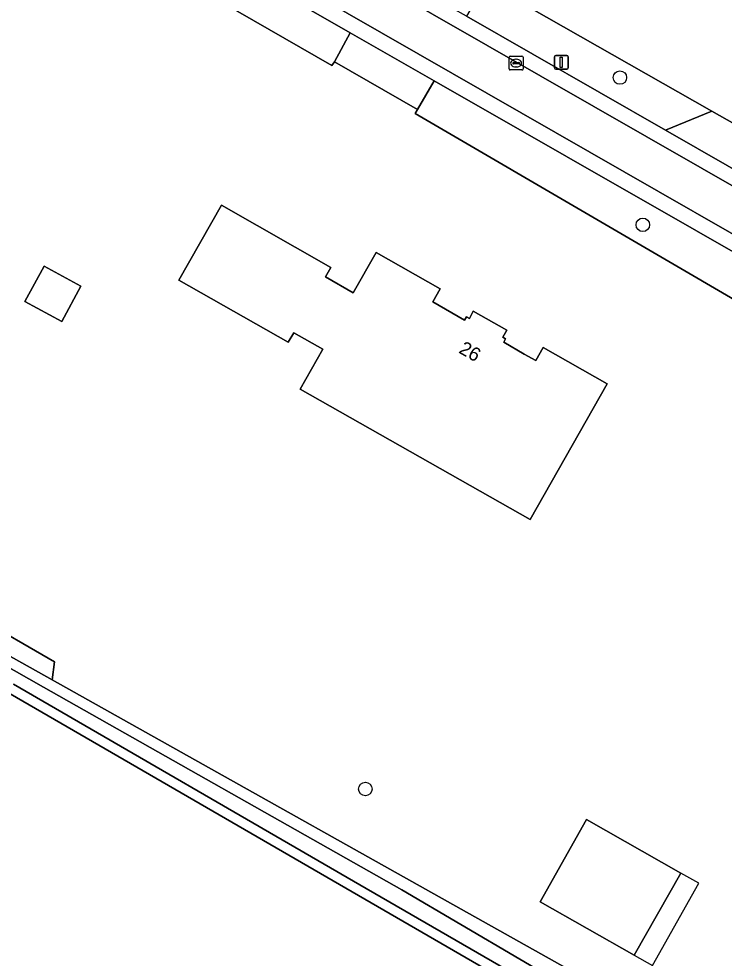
# Model space of a CAD drawing. Extents: x 156502 to 159075, y 384229 to 386100.
# Drawn here: x 157051.2 to 157102.6, y 385696.6 to 385765 of the extents above; entities that cross this region are included whole.
import ezdxf

# ---------------------------------------------------------------- set-up
doc = ezdxf.new("R2010")
doc.units = 0
for name, color, linetype in [('IMGEO_Berm_groen', 7, 'Continuous'), ('IMGEO_Boom', 7, 'Continuous'), ('IMGEO_Erf', 7, 'Continuous'), ('IMGEO_Grasland_agrarisch', 7, 'Continuous'), ('IMGEO_Groenvoorziening', 7, 'Continuous'), ('IMGEO_Hek', 7, 'Continuous'), ('IMGEO_Lichtmast', 7, 'Continuous'), ('IMGEO_Oever', 7, 'Continuous'), ('IMGEO_Pand', 7, 'Continuous'), ('IMGEO_Pand_nummerreeks', 7, 'Continuous'), ('IMGEO_Pand_overbouw', 7, 'Continuous'), ('IMGEO_Rijbaan_lokaal_gesloten', 7, 'Continuous'), ('IMGEO_Rijbaan_lokaal_halfverhard', 7, 'Continuous'), ('IMGEO_Rijbaan_lokaal_open', 7, 'Continuous'), ('IMGEO_Rioolput', 7, 'Continuous'), ('IMGEO_Waterloop', 7, 'Continuous')]:
    doc.layers.add(name, color=color, linetype=linetype)

msp = doc.modelspace()

# ---------------------------------------------------------------- linework, layer by layer
at = {"layer": 'IMGEO_Berm_groen'}
msp.add_lwpolyline([(157086.152, 385767.162), (157085.817, 385766.586), (157084.961, 385767.091), (157083.861, 385765.187), (157098.368, 385756.889), (157101.744, 385758.276)], close=True, dxfattribs=at)
at = {"layer": 'IMGEO_Boom'}
for centre in [(157095.045, 385760.722), (157096.713, 385749.995), (157076.496, 385708.898)]:
    msp.add_circle(centre, 0.489, dxfattribs=at)
at = {"layer": 'IMGEO_Erf'}
for points in [[(157048.701, 385788.533), (157057.714, 385783.415), (157062.278, 385780.824), (157070.393, 385776.216), (157073.942, 385774.201), (157084.266, 385768.252), (157086.152, 385767.162), (157101.744, 385758.276), (157104.7, 385756.591), (157109.515, 385753.847), (157111.678, 385752.607), (157114.022, 385751.264), (157119.086, 385748.362), (157121.522, 385746.887), (157123.015, 385746.039), (157125.376, 385744.699), (157127.595, 385743.439), (157130.921, 385741.579), (157131.197, 385741.421), (157144.11, 385733.995)], [(157147.432, 385715.812), (157133.773, 385723.654), (157134.821, 385725.475), (157132.597, 385726.756), (157131.792, 385725.315), (157113.077, 385736.144), (157108.687, 385738.705), (157108.063, 385741.81), (157080.131, 385758.103), (157080.304, 385758.402), (157074.239, 385761.861), (157074.046, 385761.597), (157054.491, 385772.88), (157047.62, 385771.736)], [(157042.415, 385724.776), (157053.851, 385718.152), (157053.67, 385716.85), (157130.083, 385674.016), (157162.143, 385703.286)]]:
    msp.add_lwpolyline(points, dxfattribs=at)
for points in [[(157088.51, 385728.529), (157071.737, 385738.033), (157073.388, 385740.939), (157071.275, 385742.139), (157070.88, 385741.444), (157062.916, 385745.969), (157066.013, 385751.42), (157073.979, 385746.895), (157073.583, 385746.199), (157075.603, 385745.041), (157077.286, 385747.99), (157081.958, 385745.337), (157081.417, 385744.384), (157083.732, 385743.053), (157083.873, 385743.292), (157084.077, 385743.175), (157084.364, 385743.707), (157086.808, 385742.331), (157086.514, 385741.808), (157086.713, 385741.694), (157086.579, 385741.46), (157088.072, 385740.585), (157088.91, 385740.111), (157089.452, 385741.064), (157094.116, 385738.421)], [(157054.382, 385742.96), (157051.695, 385744.412), (157053.089, 385746.991), (157055.776, 385745.538)], [(157099.476, 385702.779), (157096.086, 385696.794), (157089.222, 385700.682), (157092.613, 385706.667)]]:
    msp.add_lwpolyline(points, close=True, dxfattribs=at)
at = {"layer": 'IMGEO_Grasland_agrarisch'}
msp.add_lwpolyline([(157128.6, 385670.699), (157041.361, 385721.169), (157027.049, 385630.912), (157026.047, 385625.421)], dxfattribs=at)
at = {"layer": 'IMGEO_Groenvoorziening'}
for points in [[(157048.686, 385779.263), (157047.987, 385776.991), (157054.491, 385772.88), (157074.046, 385761.597), (157074.239, 385761.861), (157075.399, 385763.984), (157061.322, 385772.036)], [(157047.987, 385776.991), (157047.892, 385775.032), (157046.412, 385772.497), (157046.044, 385771.329), (157045.742, 385769.133), (157042.959, 385732.042), (157041.74, 385723.537), (157053.67, 385716.85), (157053.851, 385718.152), (157042.415, 385724.776), (157044.054, 385732.143), (157045.294, 385741.29), (157045.604, 385750.127), (157045.953, 385758.926), (157047.62, 385771.736), (157054.491, 385772.88)], [(157081.499, 385760.496), (157080.304, 385758.402), (157080.131, 385758.103), (157108.063, 385741.81), (157108.687, 385738.705), (157110.125, 385741.217), (157110.277, 385744.036)]]:
    msp.add_lwpolyline(points, close=True, dxfattribs=at)
at = {"layer": 'IMGEO_Hek'}
for points in [[(157074.046, 385761.597), (157054.491, 385772.88)], [(157086.152, 385767.162), (157101.744, 385758.276)], [(157108.687, 385738.705), (157108.063, 385741.81), (157080.131, 385758.103)], [(157101.744, 385758.276), (157104.7, 385756.591)]]:
    msp.add_lwpolyline(points, dxfattribs=at)
at = {"layer": 'IMGEO_Lichtmast'}
for p, q in [((157090.277, 385761.431), (157090.277, 385762.231)), ((157090.277, 385762.231), (157090.277, 385761.431)), ((157090.377, 385762.331), (157091.167, 385762.331)), ((157091.167, 385762.331), (157090.377, 385762.331)), ((157091.267, 385762.231), (157091.267, 385761.431)), ((157091.267, 385761.431), (157091.267, 385762.231)), ((157091.167, 385761.331), (157090.377, 385761.331)), ((157090.377, 385761.331), (157091.167, 385761.331))]:
    msp.add_line(p, q, dxfattribs=at)
msp.add_lwpolyline([(157090.697, 385762.206), (157090.847, 385762.206), (157090.847, 385761.456), (157090.697, 385761.456), (157090.697, 385762.206)], dxfattribs=at)
for centre, start, end in [((157090.377, 385762.231), 90, 180), ((157090.377, 385762.231), 90, 180), ((157091.167, 385762.231), 0, 90), ((157091.167, 385762.231), 360, 90), ((157090.377, 385761.431), 180, 270), ((157090.377, 385761.431), 180, 270), ((157091.167, 385761.431), 270, 0), ((157091.167, 385761.431), 270, 0)]:
    msp.add_arc(centre, 0.1, start, end, dxfattribs=at)
at = {"layer": 'IMGEO_Oever'}
for points in [[(157053.67, 385716.85), (157041.74, 385723.537)], [(157041.602, 385722.806), (157053.036, 385716.305), (157079.167, 385701.542), (157100.636, 385688.921), (157128.657, 385673.175), (157129.567, 385672.843), (157130.183, 385672.807), (157130.592, 385673.019), (157131.132, 385673.437), (157133.442, 385675.627), (157161.344, 385701.206)], [(157041.361, 385721.169), (157128.6, 385670.699)], [(157145.132, 385684.678), (157131.268, 385672.592), (157130.641, 385672.071), (157130.089, 385671.912), (157129.557, 385671.959), (157128.852, 385672.102), (157128.318, 385672.451), (157100.715, 385687.7), (157076.092, 385701.913), (157050.852, 385716.529)], [(157132.606, 385671.378), (157162.655, 385699.661), (157164.374, 385701.279), (157164.798, 385702.861), (157164.518, 385703.205), (157165.011, 385703.658), (157165.17, 385704.25), (157162.143, 385703.286), (157130.083, 385674.016), (157053.67, 385716.85)]]:
    msp.add_lwpolyline(points, dxfattribs=at)
at = {"layer": 'IMGEO_Pand'}
for points in [[(157066.013, 385751.42), (157062.916, 385745.969), (157070.88, 385741.444), (157071.275, 385742.139), (157073.388, 385740.939), (157071.737, 385738.033), (157088.51, 385728.529), (157094.116, 385738.421), (157089.452, 385741.064), (157088.91, 385740.111), (157088.072, 385740.585), (157086.579, 385741.46), (157086.713, 385741.694), (157086.514, 385741.808), (157086.808, 385742.331), (157084.364, 385743.707), (157084.077, 385743.175), (157083.873, 385743.292), (157083.732, 385743.053), (157081.417, 385744.384), (157081.958, 385745.337), (157077.286, 385747.99), (157075.603, 385745.041), (157073.583, 385746.199), (157073.979, 385746.895)], [(157051.695, 385744.412), (157054.382, 385742.96), (157055.776, 385745.538), (157053.089, 385746.991)], [(157099.476, 385702.779), (157092.613, 385706.667), (157089.222, 385700.682), (157096.086, 385696.794)]]:
    msp.add_lwpolyline(points, close=True, dxfattribs=at)
at = {"layer": 'IMGEO_Pand_overbouw'}
msp.add_lwpolyline([(157100.798, 385702.03), (157099.476, 385702.779), (157096.086, 385696.794), (157097.408, 385696.045)], close=True, dxfattribs=at)
at = {"layer": 'IMGEO_Rijbaan_lokaal_gesloten'}
for points in [[(157155.604, 385722.866), (157042.417, 385787.656)], [(157047.474, 385781.289), (157153.385, 385720.619)]]:
    msp.add_lwpolyline(points, dxfattribs=at)
at = {"layer": 'IMGEO_Rijbaan_lokaal_halfverhard'}
for points in [[(157042.417, 385787.656), (157155.604, 385722.866)], [(157156.009, 385723.887), (157148.433, 385728.196), (157142.675, 385731.515), (157129.529, 385739.04), (157126.176, 385740.973), (157123.969, 385742.234), (157121.61, 385743.581), (157120.125, 385744.429), (157117.587, 385745.884), (157112.582, 385748.755), (157110.239, 385750.099), (157105.201, 385752.99), (157098.368, 385756.889), (157083.861, 385765.187), (157082.83, 385765.787), (157073.474, 385771.108), (157068.127, 385774.18), (157061.801, 385777.83), (157055.407, 385781.512), (157048.506, 385785.444), (157044.158, 385787.921)], [(157047.474, 385781.289), (157047.846, 385779.743), (157048.686, 385779.263), (157061.322, 385772.036), (157075.399, 385763.984), (157081.499, 385760.496), (157110.277, 385744.036), (157115.815, 385740.863), (157122.692, 385736.917), (157122.862, 385737.211), (157131.139, 385732.504), (157143.135, 385725.639), (157151.556, 385720.809)], [(157153.385, 385720.619), (157047.474, 385781.289)]]:
    msp.add_lwpolyline(points, dxfattribs=at)
at = {"layer": 'IMGEO_Rijbaan_lokaal_open'}
for points in [[(157075.399, 385763.984), (157074.239, 385761.861), (157080.304, 385758.402), (157081.499, 385760.496)], [(157104.7, 385756.591), (157101.744, 385758.276), (157098.368, 385756.889), (157105.201, 385752.99)]]:
    msp.add_lwpolyline(points, close=True, dxfattribs=at)
at = {"layer": 'IMGEO_Rioolput'}
for p, q in [((157086.982, 385761.351), (157086.982, 385762.203)), ((157087.057, 385762.277), (157087.909, 385762.277)), ((157087.983, 385762.203), (157087.983, 385761.351)), ((157087.241, 385761.771), (157087.241, 385761.783)), ((157087.679, 385761.734), (157087.281, 385761.734)), ((157087.284, 385761.82), (157087.682, 385761.82)), ((157087.493, 385761.497), (157087.468, 385761.497)), ((157087.47, 385762.057), (157087.495, 385762.057)), ((157087.725, 385761.783), (157087.725, 385761.771)), ((157087.909, 385761.277), (157087.057, 385761.277))]:
    msp.add_line(p, q, dxfattribs=at)
for points in [[(157086.982, 385761.351), (157086.982, 385762.203)], [(157087.057, 385762.277), (157087.909, 385762.277)], [(157087.983, 385762.203), (157087.983, 385761.351)], [(157087.909, 385761.277), (157087.057, 385761.277)]]:
    msp.add_lwpolyline(points, dxfattribs=at)
for centre, radius, start, end in [((157087.059, 385762.201), 0.0765, 91.55205, 178.44795), ((157087.059, 385762.201), 0.0765, 91.55205, 178.44795), ((157087.907, 385762.201), 0.0765, 1.55205, 88.44795), ((157087.907, 385762.201), 0.0765, 1.55205, 88.44795), ((157087.281, 385761.78), 0.0403, 85.87752, 175.75265), ((157087.278, 385761.77), 0.0366, 178.93798, 274.71019), ((157087.682, 385761.777), 0.043, 264.86636, 352.45326), ((157087.686, 385761.782), 0.0386, 1.73085, 96.63898), ((157087.059, 385761.353), 0.0765, 181.55205, 268.44795), ((157087.059, 385761.353), 0.0765, 181.55205, 268.44795), ((157087.907, 385761.353), 0.0765, 271.55205, 358.44795), ((157087.907, 385761.353), 0.0765, 271.55205, 358.44795)]:
    msp.add_arc(centre, radius, start, end, dxfattribs=at)
for centre, major_axis, ratio, start_param, end_param in [((157087.469, 385761.777), (-0.387, 0.002), 0.722429, 4.712389, 7.853982), ((157087.494, 385761.777), (-0.39, 0.002), 0.717154, 1.570796, 4.712389)]:
    msp.add_ellipse(centre, major_axis=major_axis, ratio=ratio, start_param=start_param, end_param=end_param, dxfattribs=at)
at = {"layer": 'IMGEO_Waterloop'}
for points in [[(157161.344, 385701.206), (157133.442, 385675.627), (157131.132, 385673.437), (157130.592, 385673.019), (157130.183, 385672.807), (157129.567, 385672.843), (157128.657, 385673.175), (157100.636, 385688.921), (157079.167, 385701.542), (157053.036, 385716.305), (157041.602, 385722.806)], [(157050.852, 385716.529), (157076.092, 385701.913), (157100.715, 385687.7), (157128.318, 385672.451), (157128.852, 385672.102), (157129.557, 385671.959), (157130.089, 385671.912), (157130.641, 385672.071), (157131.268, 385672.592), (157145.132, 385684.678)]]:
    msp.add_lwpolyline(points, dxfattribs=at)

# ---------------------------------------------------------------- texts
at = {"layer": 'IMGEO_Pand_nummerreeks'}
msp.add_text('26', height=1, rotation=330.59509, dxfattribs=at).set_placement((157083.24, 385740.705))

doc.saveas('drawing.dxf')
